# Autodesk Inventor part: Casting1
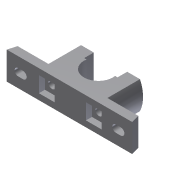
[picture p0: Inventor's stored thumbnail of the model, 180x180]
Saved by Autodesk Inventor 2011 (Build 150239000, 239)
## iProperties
Created: 2009-04
Part Number: Casting1
Document SubType Name: Modeling
Designer: Sham
Density: 1 g/cm^3
Author: Sham
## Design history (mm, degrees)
sketch "Sketch1"
  geometry: L1 (-104, 0)-(104, 0); L2 (-104, 0)-(-100, 14); L3 (-100, 14)-(100, 14); L4 (100, 14)-(104, 0); 1 further point
  constraints: 8 end point, 1 horizontal, 1 midpoint, 1 parallel, 1 other
  dimensions: "d0" = 208 distance of L1.start L1.end; "d1" = 104 distance of L1.end point (0, 0); "d2" = 4 horizontal distance of L1.start L2.end; "d3" = 4 horizontal distance of L1.end L3.end; "d10" = 14 distance between parallel lines of L1 L3
extrude "Extrusion1" new body sketch "Sketch1" stored distance "d4" = 46; taper "d5" = 0 deg
sketch "Sketch2"
  geometry: L1 (51.143, 46)-(148.857, 46); L2 (148.857, 0)-(51.143, 0); A1 r 54 centre (100, 23) between (51.143, 46) and (51.143, 0); A2 r 54 centre (100, 23) between (148.857, 0) and (148.857, 46)
  constraints: 4 end point, 4 point on circle, 2 centre point, 1 parallel
extrude "Extrusion2" join sketch "Sketch2" distance "d8" = 54; taper "d9" = 0 deg
sketch "Sketch3"
  geometry: L1 (-27.664, 68)-(-27.664, 52); L2 (-27.664, 52)-(-23.664, 52); L3 (27.664, 68)-(27.664, 52); L4 (27.664, 52)-(23.664, 52); L5 (-27.664, 68)-(27.664, 68); A1 r 24 centre (0, 48) between (-23.664, 52) and (23.664, 52); 1 further point
  constraints: 10 end point, 3 perpendicular, 2 point on circle, 1 centre point, 1 vertical alignment
  dimensions: "d11" = 16 distance of L1.start L1.end; "d12" = 4 distance from line of L2 A1.centre; "d13" = 4 distance of L1.end L2.end; "d14" = 4 distance of L3.end L4.end; "d16" = 24 radius of A1; "d17" = 16 distance of L3.start L3.end
extrude "Extrusion3" cut sketch "Sketch3" distance "d18" = 54; taper "d19" = 0 deg
sketch "Sketch4"
  geometry: L1 (-23, 29)-(-15, 29); L2 (-15, 17)-(-23, 17); L3 (-185, 29)-(-177, 29); L4 (-177, 17)-(-185, 17); A1 r 6 centre (-15, 23) between (-15, 17) and (-15, 29); A2 r 6 centre (-23, 23) between (-23, 29) and (-23, 17); A3 r 6 centre (-177, 23) between (-177, 17) and (-177, 29); A4 r 6 centre (-185, 23) between (-185, 29) and (-185, 17)
  constraints: 8 end point, 8 point on circle, 8 tangent, 4 centre point, 3 parallel
  dimensions: "d20" = 8 distance of A1.centre A2.centre; "d21" = 6 radius of A1; "d24" = 6 radius of A3; "d25" = 8 distance of A4.centre A3.centre
extrude "Extrusion4" cut sketch "Sketch4" distance "d28" = 54; taper "d29" = 0 deg
sketch "Sketch5"
  geometry: L1 (208, 0)-(0, 0) reference; L2 (53.25, -10)-(79.25, -10); L3 (79.25, -10)-(79.25, -36); L4 (79.25, -36)-(53.25, -36); L5 (53.25, -36)-(53.25, -10); L6 (131.25, -10)-(157.25, -10); L7 (157.25, -10)-(157.25, -36); L8 (157.25, -36)-(131.25, -36); L9 (131.25, -36)-(131.25, -10)
  constraints: 16 end point, 5 perpendicular, 4 parallel, 2 horizontal
  dimensions: "d30" = 26 distance of L2.start L2.end; "d31" = 10 distance between parallel lines of L2 L1; "d32" = 10 distance between parallel lines of L1 L6; "d33" = 52 distance between parallel lines of L9 L3
extrude "Extrusion5" cut sketch "Sketch5" distance "d34" = 10; taper "d35" = 0 deg
sketch "Sketch6"
  geometry: C1 r 6 at (61, 23); C2 r 6 at (139, 23); 1 further point
  constraints: 2 centre point, 1 equal radius
  dimensions: "d36" = 12 diameter of C1; "d37" = 78 distance of C2.centre C1.centre; "d39" = 39 distance of C2.centre point (100, 23)
extrude "Extrusion6" cut sketch "Sketch6" stored distance "d40" = 10; taper "d41" = 0 deg
workplane "Work Plane1"
sketch "Sketch7"
  geometry: L1 (-4, 46)-(204, 46) reference; L2 (-4, 0)-(-4, 46) reference; 1 further point
  dimensions: "d43" = 23 distance from line of L1 point (100, 23); "d44" = 104 distance from line of point (100, 23) L2
hole "Hole1" sketch "Sketch7" at (100, 23) diameter "d45" = 8; stored, may be unused: countersink angle "d49" = 90 deg, drill point angle "d51" = 118 deg; dims "d46" = 6, "d47" = 8, "d48" = 16, "d50" = 8
body "Solid1"
other parameters: "d6" = 108, "d42" = -52
